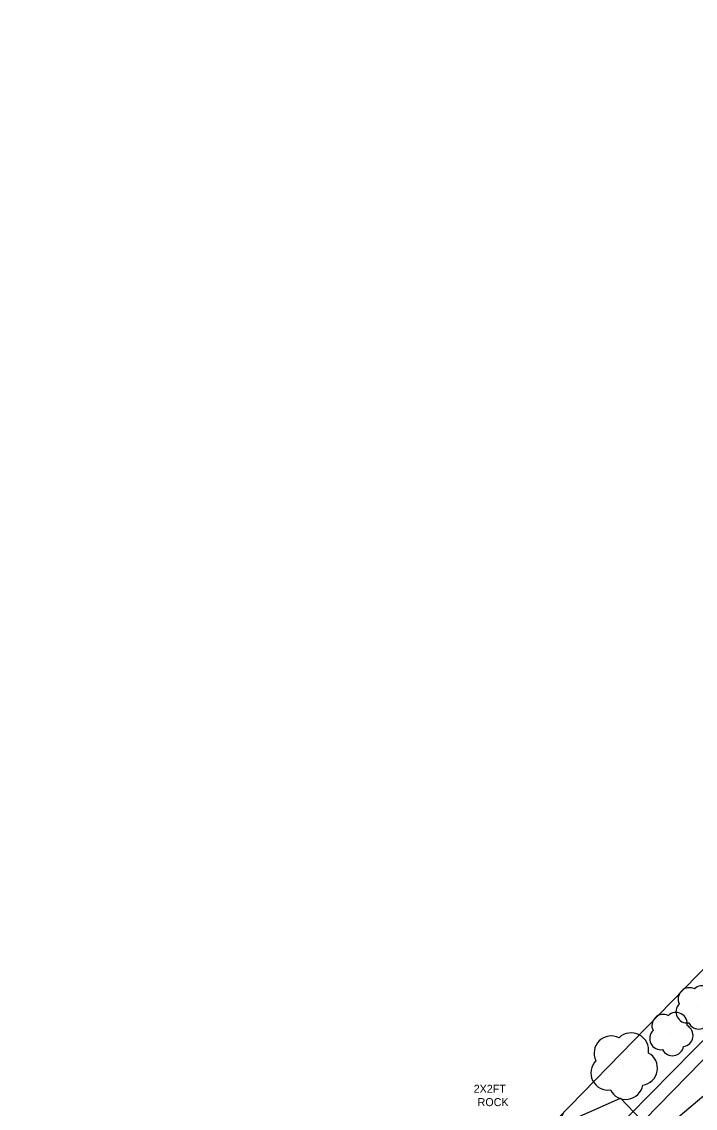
# Model space of a CAD drawing. Extents: x 2250985 to 2256614, y 13788357 to 13792478.
# Drawn here: x 2254644.8 to 2254745.6, y 13790644.2 to 13790807 of the extents above; entities that cross this region are included whole.
import ezdxf

# ---------------------------------------------------------------- set-up
doc = ezdxf.new("R2010")
doc.units = 0
for name, color, linetype in [('E_Structure_Column_COL_ANNO', 7, 'Continuous'), ('E_Structure_Fence_Rock Wall Fence_RWFN', 7, 'Continuous'), ('E_Utility_Fiber Optic_Fiber Optic Cable_FOC', 7, 'Continuous'), ('E_Vegetation_Tree_Tree_TR', 7, 'Continuous'), ('Major Contours', 7, 'Continuous')]:
    doc.layers.add(name, color=color, linetype=linetype)

# ---------------------------------------------------------------- blocks, each defined once
blk = doc.blocks.new('TR')
at = {"layer": 'E_Vegetation_Tree_Tree_TR'}
blk.add_line((0, 0), (0, 0), dxfattribs=at)
for centre, radius, start, end in [((-0.18, 0.182), 0.258, 63.1465, 206.2274), ((0.117, 0.224), 0.261, 350.8866, 133.9676), ((0.253, -0.044), 0.258, 278.5736, 61.6546), ((-0.229, -0.114), 0.258, 135.0205, 278.1015), ((0.037, -0.254), 0.258, 206.7946, 349.8756)]:
    blk.add_arc(centre, radius, start, end, dxfattribs=at)

msp = doc.modelspace()

# ---------------------------------------------------------------- linework, layer by layer
at = {"layer": 'E_Structure_Fence_Rock Wall Fence_RWFN'}
msp.add_lwpolyline([(2254761.57, 13790680.01), (2254745.99, 13790664.12), (2254723.04, 13790640.55)], dxfattribs=at)
at = {"layer": 'E_Utility_Fiber Optic_Fiber Optic Cable_FOC'}
for points in [[(2255032.95, 13790952.64), (2255003.31, 13790917.86), (2254946.65, 13790859.31), (2254901.94, 13790813.52), (2254833.06, 13790741.96), (2254719.46, 13790626.58), (2254679.73, 13790589.47), (2254575.8, 13790484.36), (2254537.8, 13790440.4), (2254506.03, 13790406.14), (2254463.43, 13790363.14), (2254414.76, 13790317.41), (2254378.78, 13790279.87), (2254273.85, 13790176.15), (2254188.13, 13790088.11), (2254093.61, 13789992.87), (2254044.6, 13789948.83), (2254024.52, 13789950.57), (2253953.86, 13790019.75)], [(2255036.19, 13790949.67), (2255006.11, 13790915.3), (2254948.5, 13790856.97), (2254903.08, 13790810.98), (2254834.19, 13790740.94), (2254720.9, 13790624.94), (2254681.69, 13790585.77), (2254577.09, 13790483.1), (2254539.49, 13790439.08), (2254507.35, 13790404.45), (2254464.72, 13790361.81), (2254418.33, 13790314.06), (2254380.92, 13790278.17), (2254276.09, 13790173.83), (2254189.76, 13790085.78), (2254096.65, 13789990.4), (2254035.89, 13789928.99), (2253999.95, 13789892.08), (2253925.3, 13789814.47), (2253839.93, 13789726.81), (2253809.07, 13789696.5), (2253784.83, 13789670.85)]]:
    msp.add_lwpolyline(points, dxfattribs=at)
at = {"layer": 'Major Contours'}
msp.add_lwpolyline([(2254725.91, 13790643.5), (2254724.76, 13790641.4), (2254734.44, 13790645.7), (2254737.51, 13790642.51), (2254730.35, 13790631.65), (2254742.98, 13790642.86), (2254742.76, 13790642.54), (2254756.65, 13790654.37), (2254756.59, 13790654.46), (2254767.31, 13790663.56), (2254773.3, 13790668.81), (2254788.87, 13790674.37), (2254795.76, 13790674.96), (2254795.85, 13790674.87), (2254796.12, 13790674.62), (2254796.24, 13790674.51), (2254791.3, 13790664.43), (2254783.57, 13790644.93), (2254784.2, 13790645.41), (2254783.32, 13790643.61), (2254776.47, 13790635.02), (2254768.98, 13790626)], dxfattribs=at)

# ---------------------------------------------------------------- block references
at = {"layer": 'E_Vegetation_Tree_Tree_TR'}
for p, xscale, yscale in [((2254745.93, 13790659.39), 6.499999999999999, 6.499999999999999), ((2254742, 13790655.39), 6.499999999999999, 6.499999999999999), ((2254734.88, 13790650.64), 10, 10)]:
    msp.add_blockref('TR', p, dxfattribs=dict(at, xscale=xscale, yscale=yscale))

# ---------------------------------------------------------------- texts
at = {"layer": 'E_Structure_Column_COL_ANNO'}
for s, p in [('2X2FT ', (2254712.46, 13790646.51)), ('ROCK ', (2254713.05, 13790644.51))]:
    msp.add_text(s, height=1.2, dxfattribs=at).set_placement(p)

doc.saveas('drawing.dxf')
